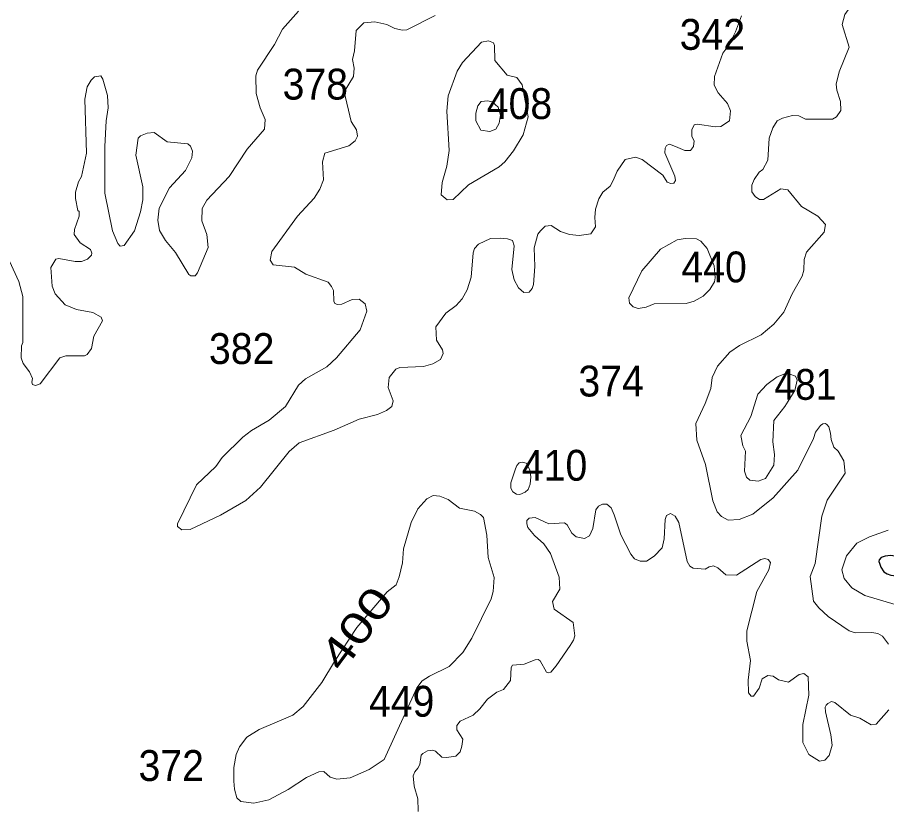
# Model space of a CAD drawing. Extents: x 499.9 to 555.3, y 9281.5 to 9336.8.
# Drawn here: x 532.51 to 537.018, y 9281.505 to 9285.624 of the extents above; entities that cross this region are included whole.
import ezdxf
from ezdxf.enums import TextEntityAlignment as Align

# ---------------------------------------------------------------- set-up
doc = ezdxf.new("R2010")
doc.units = 0
doc.header["$LTSCALE"] = 0.064
doc.layers.add('1', color=7, linetype='Continuous', lineweight=25)
doc.layers.add('2', color=7, linetype='Continuous', lineweight=13)
doc.layers.add('21', color=7, linetype='Continuous')
doc.layers.add('61', color=7, linetype='Continuous')

msp = doc.modelspace()

# ---------------------------------------------------------------- linework, layer by layer
at = {"layer": '1'}
msp.add_lwpolyline([(536.9808, 9282.7938), (536.9882, 9282.7737), (537.003, 9282.7483), (537.02, 9282.7377), (537.0401, 9282.7314), (537.0665, 9282.7282), (537.0888, 9282.7325), (537.1089, 9282.7441), (537.1152, 9282.7663), (537.1131, 9282.7907), (537.1004, 9282.8139), (537.075, 9282.8288), (537.038, 9282.833), (537.0105, 9282.8298), (536.9903, 9282.8224), (536.9787, 9282.8108), (536.9776, 9282.8023)], close=True, dxfattribs=at)
at = {"layer": '2'}
for points in [[(536.4777, 9285.1022), (536.5298, 9285.116), (536.5627, 9285.1131), (536.5972, 9285.0954), (536.7378, 9285.0955), (536.7579, 9285.1083), (536.78, 9285.1419), (536.7788, 9285.1886), (536.7596, 9285.2474), (536.7566, 9285.2776), (536.7719, 9285.3409), (536.823, 9285.4699), (536.7869, 9285.5872), (536.8016, 9285.6391), (536.8356, 9285.6869), (536.9649, 9285.8055), (536.9758, 9285.8592), (536.9713, 9285.9239), (536.9863, 9285.9717), (537.1257, 9286.1458)], [(532.9638, 9284.7118), (533.0022, 9284.5169), (533.0299, 9284.4508), (533.0424, 9284.4375), (533.0638, 9284.4412), (533.1164, 9284.5176), (533.148, 9284.6156), (533.1608, 9284.6784), (533.1608, 9284.7452), (533.1231, 9284.9093), (533.1367, 9284.9977), (533.1485, 9285.0093), (533.1827, 9285.0234), (533.2184, 9285.0266), (533.2864, 9284.9795), (533.3937, 9284.9681), (533.408, 9284.9562), (533.4171, 9284.9297), (533.414, 9284.8965), (533.3817, 9284.8306), (533.299, 9284.7402), (533.2455, 9284.6354), (533.2375, 9284.5725), (533.2472, 9284.5185), (533.2774, 9284.4675), (533.3302, 9284.4055), (533.3987, 9284.2915), (533.4088, 9284.2832), (533.4314, 9284.2839), (533.4431, 9284.299), (533.4985, 9284.4303), (533.4922, 9284.4978), (533.4668, 9284.5687), (533.4673, 9284.633), (533.4924, 9284.6766), (533.6088, 9284.7996), (533.7011, 9284.9401), (533.7907, 9285.0438), (533.7944, 9285.0946), (533.7688, 9285.1551), (533.7481, 9285.229), (533.747, 9285.3205), (533.7546, 9285.3509), (533.8422, 9285.4838), (533.8841, 9285.5623), (533.9678, 9285.6568)], [(534.6769, 9285.6331), (534.5298, 9285.5588), (534.5075, 9285.5571), (534.468, 9285.5661), (534.4264, 9285.587), (534.3642, 9285.6014), (534.3057, 9285.5965), (534.2662, 9285.5559), (534.2575, 9285.4503), (534.2468, 9285.4065), (534.2559, 9285.3612), (534.2527, 9285.3167)], [(535.6201, 9284.8264), (535.6611, 9284.8878), (535.7159, 9284.8997), (535.7508, 9284.8876), (535.857, 9284.8055), (535.8798, 9284.7696), (535.8991, 9284.7621), (535.915, 9284.7648), (535.9225, 9284.7774), (535.9192, 9284.8), (535.8673, 9284.9212), (535.8687, 9284.9458), (535.8755, 9284.9596), (535.892, 9284.9661), (535.9232, 9284.9537), (535.9711, 9284.9334), (536.0002, 9284.9335), (536.0166, 9284.955), (536.0193, 9284.9831), (536.0071, 9285.0064), (536.0069, 9285.0411), (536.0199, 9285.0662), (536.0361, 9285.0707), (536.1285, 9285.0564), (536.1578, 9285.0587), (536.2032, 9285.0869), (536.2085, 9285.139), (536.1917, 9285.1774), (536.1449, 9285.2324), (536.1235, 9285.2727), (536.1255, 9285.3176), (536.1679, 9285.4382), (536.199, 9285.48), (536.2348, 9285.5486), (536.2646, 9285.6317)], [(532.4199, 9284.4659), (532.5174, 9284.2551), (532.5372, 9284.176), (532.5386, 9283.9387), (532.5309, 9283.92), (532.5294, 9283.8588), (532.5393, 9283.8297), (532.5721, 9283.7855), (532.5874, 9283.7521), (532.5848, 9283.7328), (532.5884, 9283.7196), (532.6034, 9283.7145), (532.6272, 9283.723), (532.729, 9283.8589), (532.7601, 9283.8697), (532.8573, 9283.8681), (532.8709, 9283.8759), (532.8935, 9283.9066), (532.9066, 9283.9701), (532.9506, 9284.051), (532.9441, 9284.069), (532.9003, 9284.0936), (532.8157, 9284.1087), (532.7566, 9284.133), (532.7063, 9284.1899), (532.6899, 9284.2294), (532.6838, 9284.3276), (532.7089, 9284.37), (532.725, 9284.3742), (532.8093, 9284.3587), (532.8428, 9284.3586), (532.8725, 9284.3708), (532.8937, 9284.3912), (532.8964, 9284.4011), (532.8883, 9284.421), (532.8345, 9284.4547), (532.8047, 9284.4985), (532.8063, 9284.524), (532.83, 9284.5924), (532.8299, 9284.6171), (532.8238, 9284.6233), (532.8113, 9284.6847), (532.8112, 9284.7181), (532.827, 9284.7705), (532.8424, 9284.7987), (532.8682, 9284.9195), (532.8589, 9285.1996), (532.8711, 9285.2641), (532.8917, 9285.2986), (532.9103, 9285.3151), (532.9419, 9285.3208), (532.9532, 9285.3038)], [(532.9532, 9285.3038), (532.9762, 9285.2186), (532.9796, 9285.1543), (532.9702, 9285.0874), (532.9638, 9284.9545), (532.9638, 9284.7118)], [(534.2527, 9285.3167), (534.204, 9285.2378), (534.2414, 9285.0841), (534.2681, 9285.0417), (534.2742, 9285.0088), (534.262, 9284.9836)], [(536.3752, 9284.8357), (536.4011, 9284.8831), (536.4079, 9284.9983), (536.4282, 9285.0514), (536.45, 9285.0875), (536.4777, 9285.1022)], [(534.262, 9284.9836), (534.2285, 9284.9573), (534.1033, 9284.9194), (534.0922, 9284.8755), (534.0967, 9284.7819), (534.0774, 9284.7334), (534.0491, 9284.6864), (533.9617, 9284.5924), (533.8297, 9284.4093), (533.8204, 9284.3656), (533.8361, 9284.3414), (533.9465, 9284.3283), (534.0048, 9284.2922), (534.1212, 9284.2511), (534.1388, 9284.2277), (534.1494, 9284.2069), (534.1504, 9284.1517), (534.1553, 9284.1406), (534.1702, 9284.1349), (534.1923, 9284.1376), (534.2466, 9284.1602), (534.2827, 9284.1619), (534.3141, 9284.1388), (534.3226, 9284.1006), (534.2874, 9284.0045), (534.1638, 9283.8588), (534.1143, 9283.811), (534.0047, 9283.7488), (533.9676, 9283.7164), (533.8998, 9283.606), (533.8154, 9283.5349), (533.7246, 9283.4815), (533.6785, 9283.4469), (533.5723, 9283.3421), (533.5383, 9283.2954), (533.4393, 9283.2007), (533.3408, 9282.998), (533.3402, 9282.983), (533.3617, 9282.9662), (533.4054, 9282.9675), (533.5622, 9283.0423), (533.6941, 9283.1194), (533.7706, 9283.1872), (533.919, 9283.3734), (533.9713, 9283.4178), (534.1525, 9283.4841), (534.2816, 9283.5404), (534.3778, 9283.5647), (534.424, 9283.5848), (534.451, 9283.6053), (534.4582, 9283.6347), (534.4323, 9283.7048), (534.4381, 9283.7559), (534.4717, 9283.8), (534.4932, 9283.8078), (534.6158, 9283.8142), (534.6635, 9283.8271), (534.7041, 9283.849), (534.7172, 9283.8818), (534.7139, 9283.9008), (534.684, 9283.9498), (534.6797, 9284.0194), (534.7325, 9284.09), (534.785, 9284.13), (534.8158, 9284.1638), (534.8429, 9284.2115), (534.8639, 9284.2774), (534.8737, 9284.403), (534.8802, 9284.4252), (534.9017, 9284.4483), (534.9635, 9284.4777), (535.014, 9284.4791), (535.0517, 9284.4758), (535.0766, 9284.4668), (535.0867, 9284.4397), (535.0744, 9284.3172), (535.0866, 9284.2631), (535.1093, 9284.2218), (535.1354, 9284.198), (535.1631, 9284.1998), (535.1795, 9284.2172), (535.1871, 9284.2384), (535.1935, 9284.3323), (535.189, 9284.4293), (535.208, 9284.5), (535.222, 9284.5173), (535.2474, 9284.5407), (535.2779, 9284.5441), (535.3257, 9284.513), (535.3735, 9284.4986), (535.423, 9284.4923), (535.4841, 9284.5017), (535.5083, 9284.5379), (535.504, 9284.5859), (535.508, 9284.6294)], [(537.0273, 9282.3734), (536.9972, 9282.4145), (536.9718, 9282.4291), (536.9403, 9282.4342), (536.8551, 9282.4327), (536.8243, 9282.4426), (536.7141, 9282.5166), (536.6658, 9282.5617), (536.6378, 9282.5973), (536.6208, 9282.7251), (536.6468, 9282.7927), (536.6817, 9283.0381), (536.7103, 9283.1202), (536.8027, 9283.2597), (536.7961, 9283.3239), (536.7658, 9283.3743), (536.7437, 9283.3954), (536.7296, 9283.4347), (536.726, 9283.4672), (536.7185, 9283.5), (536.71, 9283.5112), (536.7002, 9283.5174), (536.6867, 9283.5159), (536.6754, 9283.5074), (536.6496, 9283.4729), (536.6381, 9283.4402), (536.557, 9283.2757), (536.4288, 9283.1317), (536.3241, 9283.0475), (536.2526, 9283.0202), (536.1964, 9283.0171), (536.1613, 9283.0361), (536.1395, 9283.0593), (536.1158, 9283.1164), (536.0784, 9283.3049), (536.034, 9283.4323), (536.0281, 9283.5185), (536.0775, 9283.6215), (536.1057, 9283.6989), (536.1124, 9283.7557), (536.141, 9283.8148), (536.2052, 9283.8884), (536.2549, 9283.9216), (536.3665, 9283.9782), (536.4333, 9284.0339), (536.4853, 9284.0952), (536.5274, 9284.1903), (536.5797, 9284.2821), (536.5878, 9284.3123), (536.5895, 9284.368), (536.6017, 9284.4066), (536.6936, 9284.5105), (536.7, 9284.5501), (536.6609, 9284.5939), (536.5756, 9284.6428), (536.5058, 9284.7294), (536.4687, 9284.7351), (536.3792, 9284.6802), (536.359, 9284.6802), (536.3358, 9284.6947), (536.3196, 9284.7201), (536.3192, 9284.7543), (536.3303, 9284.7825), (536.3567, 9284.8211), (536.3752, 9284.8357)], [(535.508, 9284.6294), (535.5247, 9284.6831), (535.5459, 9284.7175), (535.5835, 9284.7489), (535.5992, 9284.7787), (535.6201, 9284.8264)], [(534.5874, 9281.5051), (534.5874, 9281.5083), (534.5873, 9281.572), (534.568, 9281.6367), (534.5621, 9281.6912), (534.5701, 9281.7107), (534.586, 9281.73), (534.5965, 9281.7496), (534.6039, 9281.7982), (534.6116, 9281.807), (534.6365, 9281.8211), (534.6634, 9281.8246), (534.6789, 9281.8183), (534.7108, 9281.7872), (534.7347, 9281.7849), (534.784, 9281.7928), (534.8053, 9281.8143), (534.815, 9281.8446), (534.8193, 9281.8803), (534.7887, 9281.9293), (534.7879, 9281.9511), (534.8053, 9281.9741), (534.8732, 9282.0055), (534.908, 9282.0374), (534.9483, 9282.0889), (534.9963, 9282.1254), (535.0308, 9282.1383), (535.0674, 9282.1847), (535.0711, 9282.2521), (535.0783, 9282.2643), (535.1378, 9282.2705), (535.1952, 9282.293), (535.2108, 9282.2937), (535.2209, 9282.2875), (535.2542, 9282.2276), (535.2647, 9282.2244), (535.2761, 9282.2281), (535.3031, 9282.2608), (535.3765, 9282.3659), (535.3946, 9282.3936), (535.4015, 9282.4161), (535.3921, 9282.4867), (535.2929, 9282.5545), (535.2845, 9282.5943), (535.3233, 9282.6583), (535.3191, 9282.7206), (535.2741, 9282.844), (535.2396, 9282.8942), (535.192, 9282.9373), (535.157, 9282.9784), (535.1519, 9282.9975), (535.1519, 9283.0152), (535.1632, 9283.0275), (535.1786, 9283.0295), (535.1956, 9283.0298), (535.2657, 9282.9982), (535.3471, 9283.0022), (535.3616, 9282.993), (535.3847, 9282.9485), (535.4079, 9282.93), (535.4504, 9282.9218), (535.4776, 9282.9354), (535.4942, 9282.9733), (535.5097, 9283.0697), (535.5242, 9283.0897), (535.5447, 9283.0991), (535.5673, 9283.0989), (535.5884, 9283.0803), (535.6056, 9283.0438), (535.6395, 9282.9413), (535.6913, 9282.8409), (535.7107, 9282.8167), (535.7388, 9282.8042), (535.7727, 9282.8036), (535.8126, 9282.8306), (535.8541, 9282.8729), (535.8635, 9282.9198), (535.8685, 9283.0207), (535.8767, 9283.041), (535.8961, 9283.0511), (535.9211, 9283.0367), (535.9398, 9283.004), (535.9841, 9282.8019), (535.9974, 9282.7782), (536.0151, 9282.7677), (536.0768, 9282.7622), (536.0968, 9282.7747), (536.1195, 9282.7802), (536.1418, 9282.7702), (536.1836, 9282.7324), (536.2384, 9282.7321), (536.3658, 9282.8126), (536.3865, 9282.8175), (536.4042, 9282.8122), (536.4153, 9282.797)], [(537.0254, 9282.9643), (536.9292, 9282.9305), (536.8637, 9282.8977), (536.8103, 9282.8314), (536.7853, 9282.7585), (536.7972, 9282.7136), (536.838, 9282.6657), (536.9047, 9282.626), (537.156, 9282.5522)], [(536.4153, 9282.797), (536.4076, 9282.7589), (536.3443, 9282.646), (536.2935, 9282.443), (536.2935, 9282.3894), (536.3122, 9282.2894)], [(536.3122, 9282.2894), (536.2996, 9282.1868), (536.3019, 9282.1209), (536.3152, 9282.1039), (536.3282, 9282.1037), (536.3563, 9282.1456), (536.3728, 9282.1931), (536.4022, 9282.2113), (536.4295, 9282.2068), (536.4573, 9282.1893), (536.5084, 9282.1769), (536.5635, 9282.2167), (536.5892, 9282.2206), (536.611, 9282.2033), (536.6147, 9282.1088), (536.583, 9281.9577), (536.583, 9281.8638), (536.6136, 9281.8008), (536.6705, 9281.7667), (536.6974, 9281.7725), (536.7197, 9281.7963), (536.7352, 9281.85), (536.729, 9281.9027), (536.7007, 9282.0222), (536.6991, 9282.0462), (536.7037, 9282.0579), (536.7133, 9282.0655), (536.7327, 9282.0758), (536.7497, 9282.0704), (536.8302, 9282.0053), (536.8797, 9281.9898), (536.9377, 9281.956), (536.9641, 9281.9578), (537.029, 9282.0329)]]:
    msp.add_lwpolyline(points, dxfattribs=at)
for points in [[(535.0832, 9284.9323), (535.1324, 9285.0157), (535.1591, 9285.108), (535.1283, 9285.2745), (535.0993, 9285.3131), (535.0495, 9285.3252), (534.985, 9285.4012), (534.9848, 9285.4779), (534.9781, 9285.4929), (534.9532, 9285.5025), (534.9168, 9285.4951), (534.8185, 9285.3904), (534.7897, 9285.3454), (534.7433, 9285.2179), (534.7368, 9285.1383), (534.7494, 9284.9346), (534.7367, 9284.8519), (534.7127, 9284.7684), (534.7082, 9284.7032), (534.7378, 9284.6773), (534.7692, 9284.6798), (534.8493, 9284.7562), (535.0087, 9284.8482), (535.0375, 9284.8742)], [(534.913, 9285.0398), (534.8876, 9285.0879), (534.8874, 9285.1276), (534.8981, 9285.1658), (534.9156, 9285.1878), (534.9498, 9285.1914), (534.9721, 9285.1864), (535.0029, 9285.1582), (535.015, 9285.1172), (535.009, 9285.0759), (534.9918, 9285.0441), (534.9595, 9285.0326)], [(535.6813, 9284.1689), (535.7475, 9284.31), (535.8454, 9284.4224), (535.9313, 9284.471), (535.9726, 9284.4778), (536.0313, 9284.4758), (536.055, 9284.4628), (536.0866, 9284.4247), (536.1228, 9284.3362), (536.1293, 9284.2732), (536.1244, 9284.2534), (536.1001, 9284.2137), (536.0666, 9284.1783), (536.0202, 9284.1521), (535.979, 9284.1407), (535.8121, 9284.1388), (535.7712, 9284.1215), (535.73, 9284.1136), (535.7034, 9284.1227), (535.6839, 9284.1423)], [(536.2612, 9283.4551), (536.3134, 9283.5545), (536.3496, 9283.6696), (536.3959, 9283.7204), (536.4501, 9283.7608), (536.4904, 9283.7753), (536.5162, 9283.7743), (536.5459, 9283.7636), (536.5535, 9283.742), (536.5412, 9283.6895), (536.4896, 9283.6069), (536.4334, 9283.5331), (536.4271, 9283.4234), (536.4364, 9283.3566), (536.4332, 9283.301), (536.3897, 9283.2328), (536.3521, 9283.2191), (536.3088, 9283.2236), (536.2916, 9283.2388), (536.2806, 9283.2706), (536.2852, 9283.3741), (536.2726, 9283.402)], [(535.0932, 9283.2823), (535.0695, 9283.2103), (535.0695, 9283.1819), (535.0799, 9283.1639), (535.0979, 9283.1516), (535.1149, 9283.1497), (535.1433, 9283.1611), (535.1594, 9283.1762), (535.1689, 9283.2027), (535.1718, 9283.2406), (535.168, 9283.2775), (535.149, 9283.3116), (535.1291, 9283.3182), (535.1121, 9283.3135), (535.1007, 9283.2993)], [(534.4127, 9281.7754), (534.5808, 9282.1462), (534.6097, 9282.1825), (534.6471, 9282.2076), (534.7484, 9282.2581), (534.8201, 9282.3295), (534.8672, 9282.404), (534.967, 9282.6094), (534.9767, 9282.6474), (534.9818, 9282.7185), (534.9504, 9282.8236), (534.9436, 9282.9388), (534.9271, 9283.03), (534.9107, 9283.0465), (534.88, 9283.0628), (534.8031, 9283.0794), (534.7431, 9283.1233), (534.701, 9283.1409), (534.6668, 9283.1438), (534.6333, 9283.1274), (534.5856, 9283.0756), (534.5516, 9283.004), (534.5116, 9282.8686), (534.5074, 9282.7949), (534.49, 9282.7227), (534.4734, 9282.6815), (534.4282, 9282.6453), (534.2709, 9282.4591), (534.1534, 9282.2837), (534.0883, 9282.1752), (533.9909, 9282.0499), (533.9378, 9282.0046), (533.7634, 9281.9316), (533.7004, 9281.8909), (533.6617, 9281.8404), (533.6446, 9281.8007), (533.6324, 9281.7332), (533.6323, 9281.6624), (533.635, 9281.6219), (533.6478, 9281.576), (533.669, 9281.5575), (533.7355, 9281.5495), (533.8143, 9281.5657), (533.9133, 9281.6191), (534.0095, 9281.6815), (534.0731, 9281.711), (534.0983, 9281.7129), (534.1314, 9281.6836), (534.1663, 9281.6738), (534.2353, 9281.6796), (534.3346, 9281.723)]]:
    msp.add_lwpolyline(points, close=True, dxfattribs=at)

# ---------------------------------------------------------------- texts
at = {"layer": '21'}
for s, width, p in [('342', 0.95, (535.9447, 9285.4559)), ('378', 0.95, (533.8849, 9285.198)), ('408', 0.95, (534.9441, 9285.097)), ('440', 0.95, (535.9536, 9284.2499)), ('382', 0.95, (533.5032, 9283.8265)), ('374', 0.95, (535.4192, 9283.658)), ('481', 0.9, (536.4363, 9283.6408)), ('410', 0.95, (535.1261, 9283.2213)), ('449', 0.95, (534.3331, 9281.9974)), ('372', 0.95, (533.1379, 9281.6641))]:
    msp.add_text(s, height=0.16, dxfattribs=dict(at, width=width)).set_placement(p)
at = {"layer": '61', "width": 1.3}
msp.add_text('400', height=0.16, rotation=53.409, dxfattribs=at).set_placement((534.3329, 9282.4083), align=Align.CENTER)

doc.saveas('drawing.dxf')
